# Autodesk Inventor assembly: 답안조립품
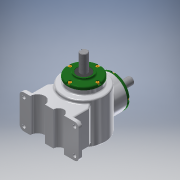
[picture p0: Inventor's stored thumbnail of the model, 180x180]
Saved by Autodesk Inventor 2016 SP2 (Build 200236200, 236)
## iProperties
Created: 2018-08
Part Number: 답안조립품
Document SubType Name: Assembly
Designer: Administrator
Author: Administrator
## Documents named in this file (14)
- Z:\ATC마스터자격증시험\480807V1002 이시화(인벤터)\답안조립품.iam
- Z:\ATC마스터자격증시험\480807V1002 이시화(인벤터)\본체.ipt
- Z:\ATC마스터자격증시험\480807V1002 이시화(인벤터)\커버.ipt
- Z:\ATC마스터자격증시험\480807V1002 이시화(인벤터)\베어링 6203.ipt
- Z:\ATC마스터자격증시험\480807V1002 이시화(인벤터)\메인 축.ipt
- 메인 축.ipt
- Z:\ATC마스터자격증시험\480807V1002 이시화(인벤터)\키 5x5.ipt
- Z:\ATC마스터자격증시험\480807V1002 이시화(인벤터)\오일실 17 32 8.ipt
- Z:\ATC마스터자격증시험\480807V1002 이시화(인벤터)\서브 축.ipt
- 서브 축.ipt
- Z:\ATC마스터자격증시험\480807V1002 이시화(인벤터)\키 4x4.ipt
- Z:\ATC마스터자격증시험\480807V1002 이시화(인벤터)\메인 베벨기어.ipt
- Z:\ATC마스터자격증시험\480807V1002 이시화(인벤터)\서브 베벨기어.ipt
- Z:\ATC마스터자격증시험\480807V1002 이시화(인벤터)\볼트 M4.ipt
